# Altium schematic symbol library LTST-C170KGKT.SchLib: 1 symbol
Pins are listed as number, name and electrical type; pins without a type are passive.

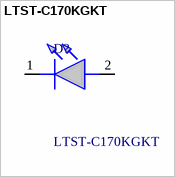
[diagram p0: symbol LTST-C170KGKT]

## LTST-C170KGKT
designator D?
LED,SMD,0805,Green,35mcd,130deg Lite-On LTST-C170KGKT, CHIPLED 0805 Series Green LED, 571 nm 2012 (0805), Rectangle Lens SMD package; Geometry.Height: 1.1mm
footprint LEDC2012X110N
pins: 1 K, 2 A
